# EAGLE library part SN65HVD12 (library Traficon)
3.3V RS485 transceiver
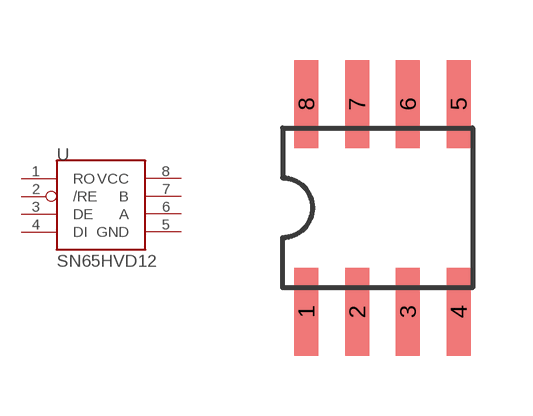
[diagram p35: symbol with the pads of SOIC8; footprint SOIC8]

Designator prefix U

## SN65HVD12  [SOIC8]
1  RO  out
2  /RE  in
3  DE  in
4  DI  in
5  GND  pas
6  A
7  B
8  VCC  pas

## Footprint SOIC8 (pad centres in mm)
Small Outline IC
smd 0.6 x 2.2: 1 -1.905,-2.6; 2 -0.635,-2.6; 3 0.635,-2.6; 4 1.905,-2.6; 5 1.905,2.6; 6 0.635,2.6; 7 -0.635,2.6; 8 -1.905,2.6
